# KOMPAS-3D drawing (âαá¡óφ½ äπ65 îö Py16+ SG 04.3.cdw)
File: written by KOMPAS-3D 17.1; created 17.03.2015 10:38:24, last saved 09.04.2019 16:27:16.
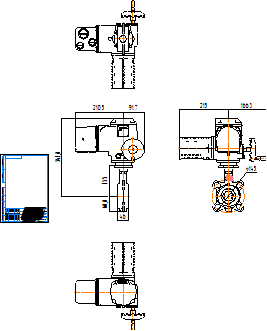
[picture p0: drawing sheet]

Sheet 1: A4, portrait

Title block, sheet 1: name: Гранвэл Ду65 МФ Py16+ SG 04.3; material: Внимание! Данный продукт является объектом авторского права ООО «Торговый Дом АДЛ». / Запрещается изменение, копирование, распространение / (в том числе путем копирования на другие сайты и ресурсы в Интернете) / или любое иное использование информации и объектов без предварительного / согласия правообладателя (ООО «Торговый Дом АДЛ»).; mass: 43,9; sheets: 1; organisation: ООО "Торговый дом АДЛ"; sheet format: A4; stored path: \\adlc.lan\data\АДЛ_ПКД\3D-модели\ADL production\Дисковые поворотные затворы ГРАНВЭЛ\межфланцевый с эл.приводом Auma Ру 16\KOMPAS 2D\Гранвэл Ду65 МФ Py16+ SG 04.3.cdw

Views: Проекционный вид 2, Проекционный вид 3, Проекционный вид 4
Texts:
  Klimkovich
  ADL
Dimensions and other numbers on the sheet: 166,3; 215; 145; 1:1; 1; 43,9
